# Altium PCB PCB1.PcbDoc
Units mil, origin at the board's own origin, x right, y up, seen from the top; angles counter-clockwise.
Board outline 3942.06 x 5904.05 mil, 2 copper layers (Top Layer, Bottom Layer); 24 components, 64 nets, 315 pads, 153 vias.
Unrouted connection lines stored in the file: 55.
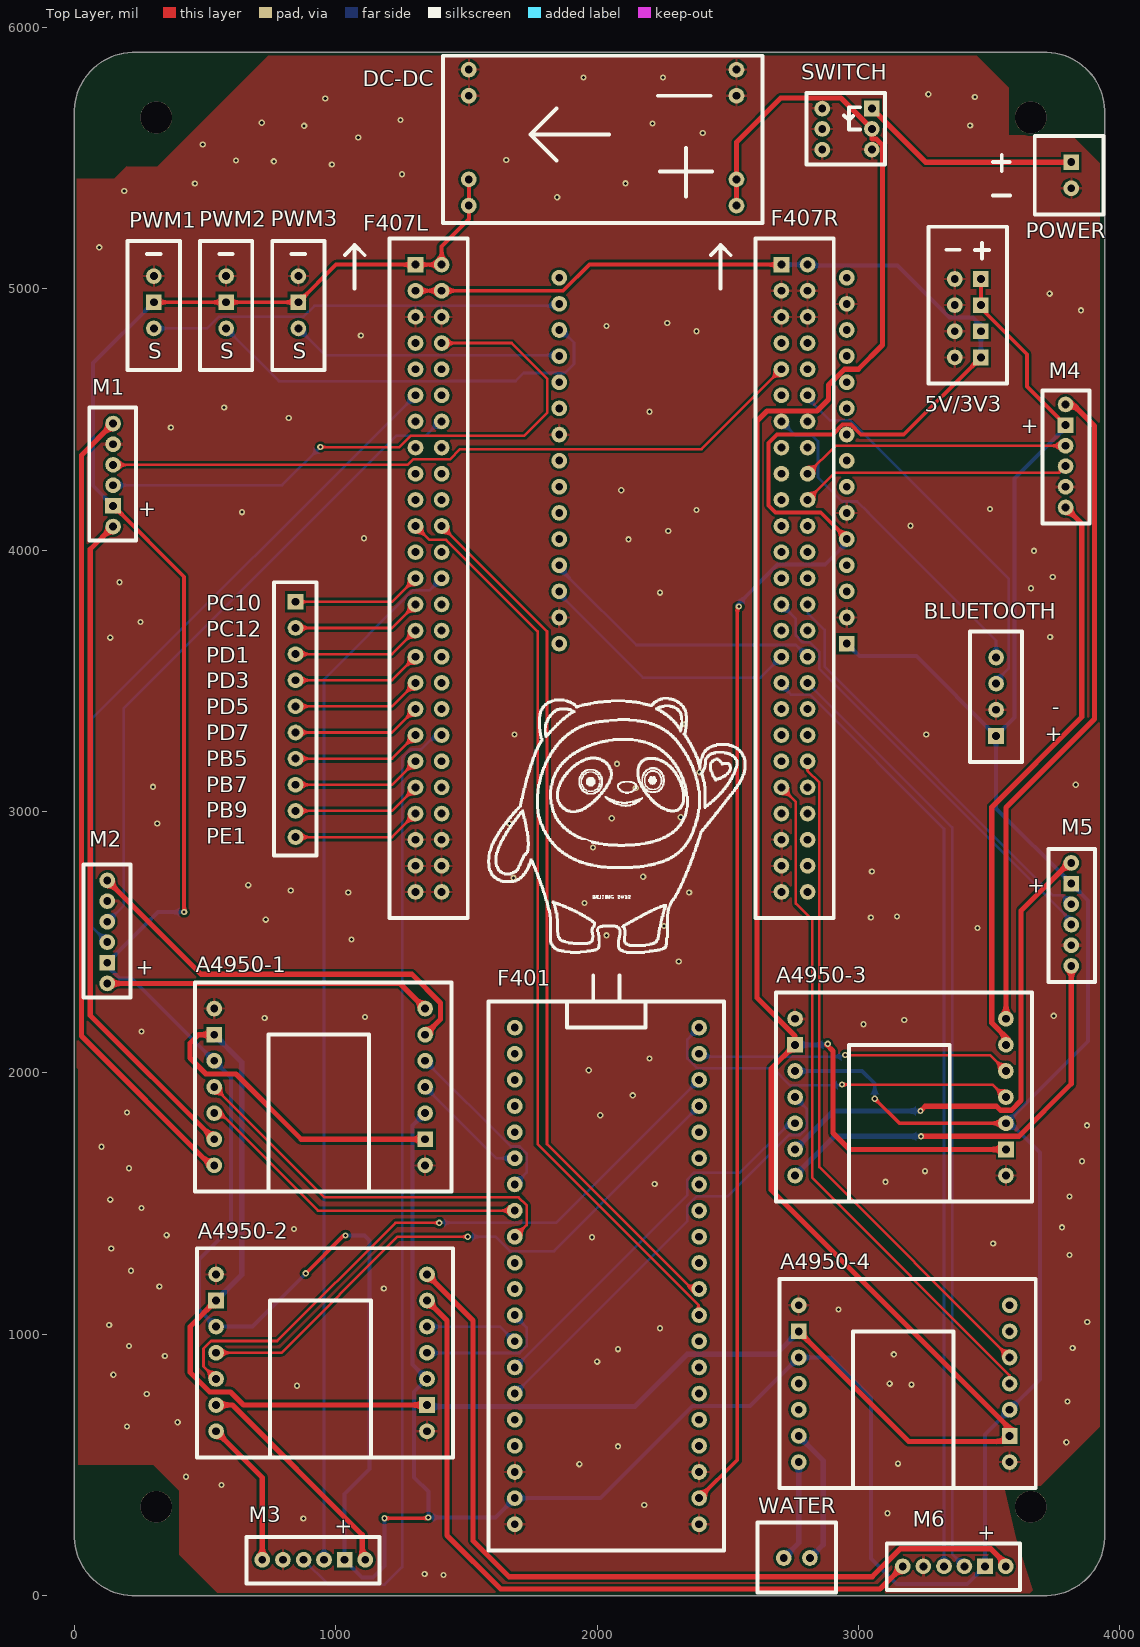
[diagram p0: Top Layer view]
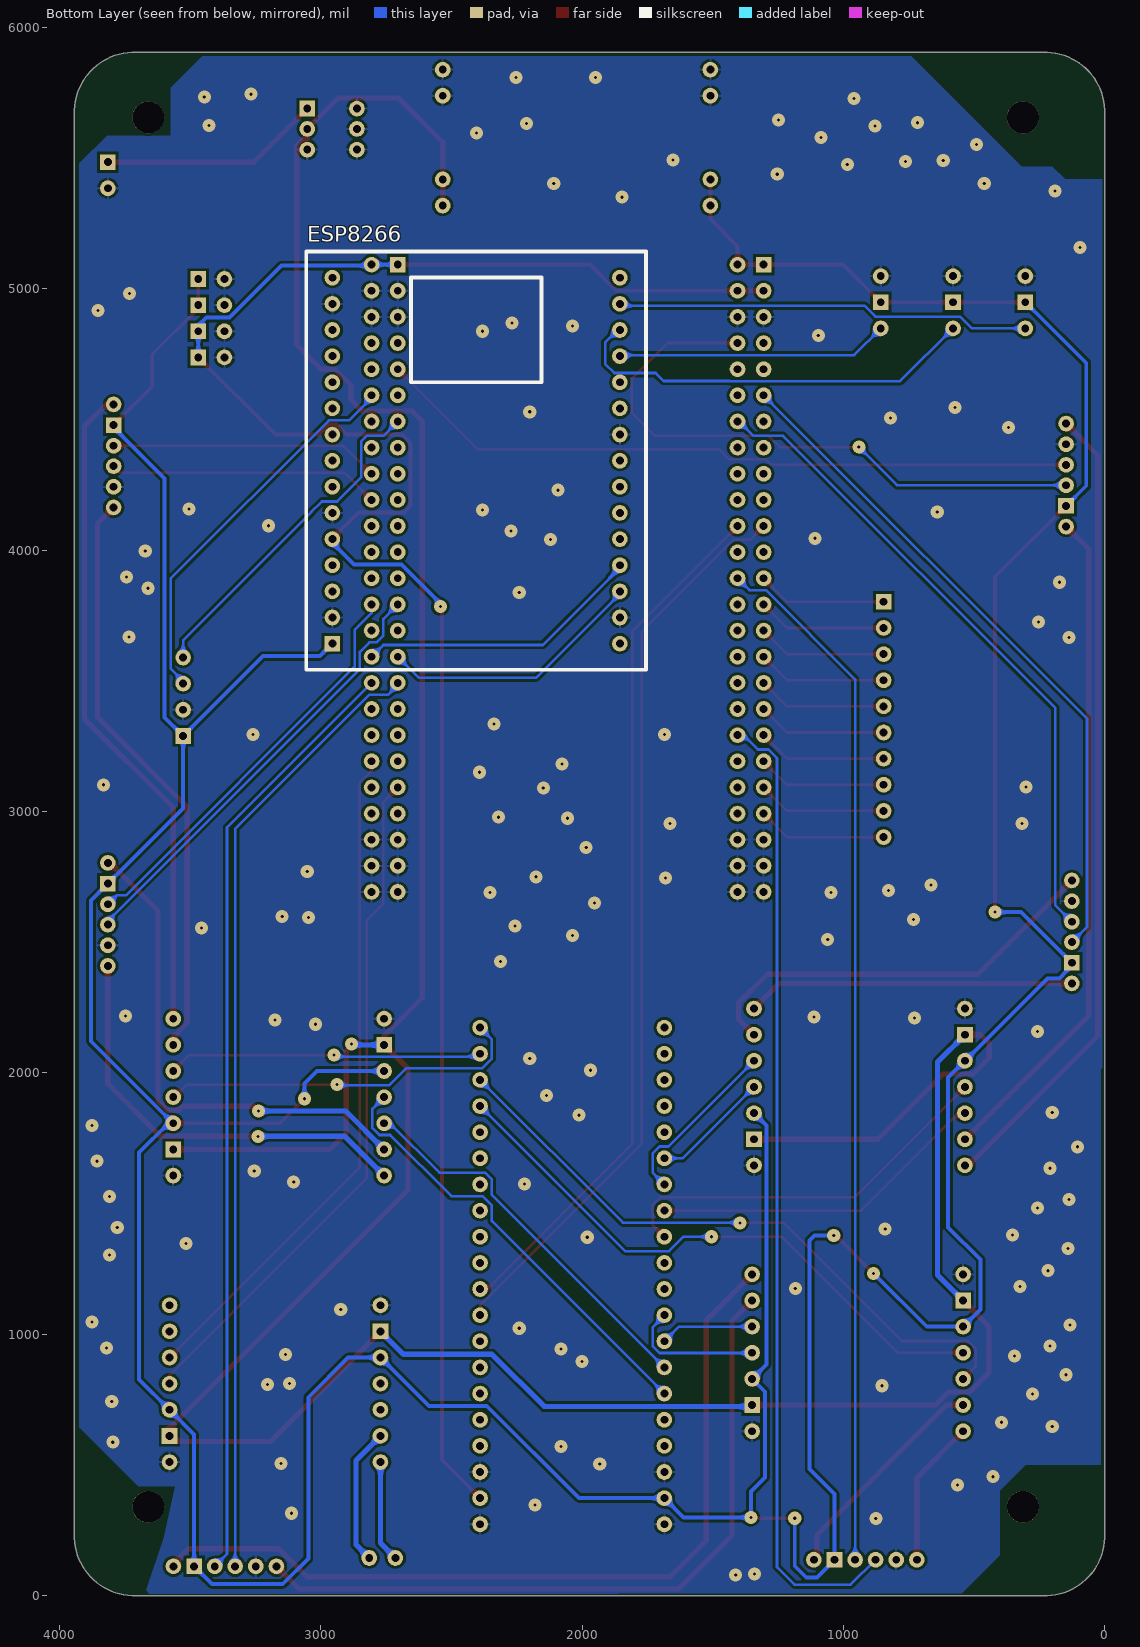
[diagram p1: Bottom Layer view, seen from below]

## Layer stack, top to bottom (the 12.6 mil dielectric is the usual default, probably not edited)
Top Solder: solder mask 0.4, Solder Resist, Dk 3.5
Top Layer: signal copper 1.4
Dielectric 1: dielectric 12.6, FR-4, Dk 4.8
Bottom Layer: signal copper 1.4
Bottom Solder: solder mask 0.4, Solder Resist, Dk 3.5

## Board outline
220,0 cw(c228.5,228.5) 0,237 0,236.11 0,5684 cw(c228.5,5675.5) 237,5904 3722.01,5904 cw(c3713.51,5675.5) 3942.01,5667 3942.01,5666 3942.01,219 3942,220 cw(c3713.5,228.5) 3705,0

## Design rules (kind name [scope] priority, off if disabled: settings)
Clearance [All] p1: gap=10 ignorepadtopadclearanceinfootprint=FALSE except(0.25: Arc-Arc Arc-Track Arc-SMDPad Arc-THPad Arc-Via Arc-Text Arc-Hole Track-Track Track-SMDPad Track-THPad Track-Via Track-Text Track-Hole SMDPad-SMDPad SMDPad-THPad SMDPad-Via SMDPad-Text SMDPad-Hole THPad-THPad THPad-Via THPad-Text THPad-Hole Via-Via Via-Text Via-Hole Text-Text Text-Hole)
HoleSize [All] p1: absolutevalues=TRUE maxlimit=130 minlimit=1 maxpercent=80.000 minpercent=20.000
PolygonConnect [All] p1: thpad.connectstyle=Relief thpad.reliefconductorwidth=10 thpad.reliefentries=4 thpad.polygonreliefangle="90 Angle" thpad.airgapwidth=10 smdpad.connectstyle=Relief smdpad.reliefconductorwidth=10 smdpad.reliefentries=4 smdpad.polygonreliefangle="90 Angle" smdpad.airgapwidth=10 via.connectstyle=Direct via.reliefconductorwidth=10 via.reliefentries=4 via.polygonreliefangle="90 Angle" via.airgapwidth=10
RoutingVias [All] p1: holewidth=28 width=50 viastyle="Through Hole" minholewidth=28 minwidth=50 maxholewidth=28 maxwidth=50
SilkToSolderMaskClearance [IsPad] p1: minsilkscreentomaskgap=7 clearancetoexposedcopper=TRUE
SolderMaskExpansion [All] p1: expansion=4
Width Width_4 [All] p1: maxlimit=20 minlimit=10 preferedwidth=10
Width Width_3 [InNet('3V3')] p2: maxlimit=15 minlimit=10 preferedwidth=15
Width Width_2 [InNet('5V')] p3: maxlimit=15 minlimit=15 preferedwidth=15
Width Width_1 [InNet('12V')] p4: maxlimit=20 minlimit=10 preferedwidth=20
Width [InNet('12V_IN')] p5: maxlimit=20 minlimit=10 preferedwidth=20
28 further rules are at their usual default settings.

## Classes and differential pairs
component class Sheet1: DC-DC POWER SWITCH

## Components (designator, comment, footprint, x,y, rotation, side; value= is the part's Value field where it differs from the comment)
*1 "PIN_HEADER" PIN_HEADER -9460,-15590 r0 top
*2 "POWER_HEADER" POWER_HEADER 3468,5137 r0 top
A4950-1 "A4950" A4950 962,2191 r180 top (schematic designator *5)
A4950-2 "A4950" A4950 969,1174 r180 top (schematic designator *6)
A4950-3 "A4950" A4950 3184,2152 r180 top (schematic designator *7)
A4950-4 "A4950" A4950 3198,1056 r180 top (schematic designator *8)
BLUETOOTH "HC-06" HC-06 3718,3582 r180 top (schematic designator *11)
DC-DC "DC-DC" DC-DC 1902,5412 r180 top (schematic designator *9)
ESP8266 "ESP8266" ESP 1894,3008 r180 bottom (schematic designator *22)
F401 "STM32F401" STM32F401CCU6 2290,273 r0 top (schematic designator *21)
F407L "STM32F407左" STM32F407左 1305,3992 r0 top (schematic designator *19)
F407R "STM32F407右" STM32F407左 2705,3992 r0 top locked (schematic designator *18)
M1 "ENCODER1" ENCODER1 148,4090 r0 top (schematic designator *15)
M2 "ENCODER2" ENCODER1 126,2342 r0 top (schematic designator *16)
M3 "ENCODER3" ENCODER1 1113,137 r90 top (schematic designator *17)
M4 "ENCODER4" ENCODER2 3813,4155 r0 top (schematic designator *12)
M5 "ENCODER5" ENCODER2 3835,2401 r0 top (schematic designator *13)
M6 "ENCODER6" ENCODER2 3161,91 r270 top (schematic designator *14)
POWER "POWER" POWER 3814,5384 r0 top (schematic designator *10)
PWM1 "PWM1" PWM 1004,3548 r0 top (schematic designator *20)
PWM2 "PWM2" PWM 1280.5,3548 r0 top (schematic designator *23)
PWM3 "PWM3" PWM 1557,3548 r0 top (schematic designator *24)
SWITCH "SWITCH" SIWITCH 2951,5689 r0 top (schematic designator *3)
WATER "WATER_MOTER" WATER_HEADER 2814,144 r90 top (schematic designator *4)

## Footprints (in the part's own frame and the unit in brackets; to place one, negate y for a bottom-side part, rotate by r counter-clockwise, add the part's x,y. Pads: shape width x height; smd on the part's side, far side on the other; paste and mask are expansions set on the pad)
A4950 [mil]
  round 60 hole 30: 1(-380,545) 3(-380,345) 4(-380,245) 5(-380,145) 6(-380,45) 7(-380,-55) 8(427,545) 9(427,445) 10(427,345) 11(427,245) 12(427,145) 14(427,-55)
  rect 60x60 hole 30: 2(-380,445) 13(427,45)
  silkscreen extent -480,-155 500,645
DC-DC [mil]
  round 60 hole 30: 1(-631,-426) 2(-631,-326) 3(-631,-6) 4(-631,94) 5(393,-426) 6(393,-326) 7(393,-6) 8(393,94)
  silkscreen extent -731,-479 492,160
ENCODER1 [mil]
  round 60 hole 30: 1(0,394) 2(0,315) 3(0,236) 4(0,158) 6(0,0)
  rect 60x60 hole 30: 5(0,79)
  silkscreen extent -91,-54 88,455
ENCODER2 [mil]
  round 60 hole 30: 1(-21,8) 2(-21,87) 3(-21,166) 4(-21,244) 6(-21,402)
  rect 60x60 hole 30: 5(-21,323)
  silkscreen extent -109,-53 70,456
ESP [mil]
  round 60 hole 30: 1(-1061,2034) 2(-1061,1934) 3(-1061,1834) 4(-1061,1734) 5(-1061,1634) 6(-1061,1534) 7(-1061,1434) 8(-1061,1334) 9(-1061,1234) 10(-1061,1134) 11(-1061,1034) 12(-1061,934) 13(-1061,834) 14(-1061,734) 16(39,2034) 17(39,1934) 18(39,1834) 19(39,1734) 20(39,1634) 21(39,1534) 22(39,1434) 23(39,1334) 24(39,1234) 25(39,1134) 26(39,1034) 27(39,934) 28(39,834) 29(39,734) 30(39,634)
  rect 60x60 hole 30: 15(-1061,634)
  silkscreen extent -1161,534 139,2134
HC-06 [mil]
  round 60 hole 30: 1(192,-7) 2(192,93) 3(192,193)
  rect 60x60 hole 30: 4(192,293)
  silkscreen extent 92,-107 292,393
PIN_HEADER [mil]
  rect 60x60 hole 30: 1(10306,19392)
  round 60 hole 30: 2(10306,19292) 3(10306,19192) 4(10306,19092) 5(10306,18992) 6(10306,18892) 7(10306,18792) 8(10306,18692) 9(10306,18592) 10(10306,18492)
  silkscreen extent 10224,18422 10386,19467
POWER [mil]
  rect 60x60 hole 30: 1(0,100)
  round 60 hole 30: 2(0,0)
  silkscreen extent -300,-100 123,200
POWER_HEADER [mil]
  rect 60x60 hole 30: 1(0,-100) 2(0,-200) 3(0,-300) 4(0,-400)
  round 60 hole 30: 5(-100,-100) 6(-100,-200) 7(-100,-300) 8(-100,-400)
  silkscreen extent -200,-500 100,100
PWM [mil]
  round 60 hole 30: 1(-700,1500) 3(-700,1300)
  rect 60x60 hole 30: 2(-700,1400)
  silkscreen extent -800,1141 -600,1634
SIWITCH [mil]
  rect 60x60 hole 30: 1(100,0)
  round 60 hole 30: 2(100,-78) 3(100,-157) 4(-90,0) 5(-90,-78) 6(-90,-157)
  silkscreen extent -150,-214 150,60
STM32F401CCU6 [mil]
  round 60 hole 30: 1(-605,1900) 2(-605,1800) 3(-605,1700) 4(-605,1600) 5(-605,1500) 6(-605,1400) 7(-605,1300) 8(-605,1200) 9(-605,1100) 10(-605,1000) 11(-605,900) 12(-605,800) 13(-605,700) 14(-605,600) 15(-605,500) 16(-605,400) 17(-605,300) 18(-605,200) 19(-605,100) 20(-605,0) 21(100,1900) 22(100,1800) 23(100,1700) 24(100,1600) 25(100,1500) 26(100,1400) 27(100,1300) 28(100,1200) 29(100,1100) 30(100,1000) 31(100,900) 32(100,800) 33(100,700) 34(100,600) 35(100,500) 36(100,400) 37(100,300) 38(100,200) 39(100,100) 40(100,0)
  silkscreen extent -705,-100 195,2100
STM32F407左 [mil]
  rect 60x60 hole 30: 1(0,1100)
  round 60 hole 30: 2(0,1000) 3(0,900) 4(0,800) 5(0,700) 6(0,600) 7(0,500) 8(0,400) 9(0,300) 10(0,200) 11(0,100) 12(0,0) 13(0,-100) 14(0,-200) 15(0,-300) 16(0,-400) 17(0,-500) 18(0,-600) 19(0,-700) 20(0,-800) 21(0,-900) 22(0,-1000) 23(100,1100) 24(100,1000) 25(100,900) 26(100,800) 27(100,700) 28(100,600) 29(100,500) 30(100,400) 31(100,300) 32(100,200) 33(100,100) 34(100,0) 35(100,-100) 36(100,-200) 37(100,-300) 38(100,-400) 39(100,-500) 40(100,-600) 41(100,-700) 42(100,-800) 43(100,-900) 44(100,-1000) 45(0,-1100) 46(0,-1200) 47(0,-1300) 48(100,-1100) 49(100,-1200) 50(100,-1300)
  silkscreen extent -270,-1400 200,1200
WATER_HEADER [mil]
  round 60 hole 30: 1(0,100) 2(0,0)
  silkscreen extent -132,-100 135,200

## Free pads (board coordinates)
  round 122 hole 122: 75(313,340) 75(313,5655) 75(3659,340) 75(3659,5655)

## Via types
v1: diameter 24/50 (per signal layer), hole 12, Top Layer to Bottom Layer, 153 vias

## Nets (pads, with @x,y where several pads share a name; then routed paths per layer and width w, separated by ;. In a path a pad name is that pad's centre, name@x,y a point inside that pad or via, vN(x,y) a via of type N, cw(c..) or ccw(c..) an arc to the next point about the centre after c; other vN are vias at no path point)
3V3: *2.3 *2.4 ESP8266.11 F401.39 F407L.2 F407L.24 F407R.1 F407R.23 | length 7991
  Top Layer w15: F407L.2 F407L.24 1870,4992 1970,5092 F407R.1 ; F401.39 2536,519 v1@2536,3784 ; ESP8266.11@2964,4036 2855.5,4144.5 2681.5,4144.5 2656,4170 2656,4410.18 2687.82,4442 2901.61,4442 2939.36,4479.75 2970.64,4479.75 3008.39,4442 3173,4442 *2.4
  Bottom Layer w15: v1@2534,3788.18 2690.32,3944.5 2872.5,3944.5 ESP8266.11@2951,4023 ; F407R.1 F407R.23 2809,5088 3149.82,5088 3348.32,4889.5 3437.5,4889.5 3468,4859 *2.3 *2.4
  other v1: 2542,3784
5V: *2.1 *2.2 A4950-1.3 A4950-1.12 A4950-2.3 A4950-2.12 A4950-3.3 A4950-3.12 A4950-4.3 A4950-4.12 BLUETOOTH.4 DC-DC.7 DC-DC.8 ESP8266.15 F401.19 F407L.1 F407L.23 M1.5 M2.5 M3.5 M4.5 M5.5 M6.5 PWM1.2 PWM2.2 PWM3.2 | length 20760.1
  Top Layer w15: M1.5 149,4169 420,3898 v1(420,2615) ; PWM1.2 PWM2.2 PWM3.2 1001,5092 F407L.1 F407L.23 1405,5162 1509,5266 DC-DC.8 DC-DC.7 ; v1(885,1233) v1@1027,1375 ; v1(1186,296) 1351,296 v1(1354,299) ; A4950-1.3 A4950-1.3@1345.5,1842.5 ; v1(3062,1901) 3156,1807 A4950-3.3 ; *2.1 *2.2 3462,4931 3644,4749 3644,4626 M4.5
  Bottom Layer w15: M2.5 126,2408 144.5,2389.5 145.68,2389.5 173.5,2361.68 219.32,2361.68 A4950-1.12 599,1982 599,1409 476,1286 476,1095 A4950-2.12 681,1029 v1(885,1233) ; M2.5@127,2422 320,2615 v1(420,2615) ; M1.5 71,4246 71,4715 PWM1.2 ; v1(1037,1378) 1110,1378 1129,1359 1129,484 1034,389 M3.5 1101,70 1142,70 1186,114 v1(1186,296) v1@1182,296 ; A4950-1.3 1294,1798 1294,884 A4950-2.3 1300,780 1300,452 1354,398 v1(1354,299) 1611,299 F401.19 ; F401.19@1675,383 F401.19 ; A4950-3.12 3014,2007 3062,1959 v1(3062,1901) ; ESP8266.15 3003,3594 3221,3594 BLUETOOTH.4 ; M4.5@3792,4498 M4.5 3792,4469 3596.5,4273.5 3596.5,3359.5 BLUETOOTH.4 ; F401.19 2012,373 2364.5,725.5 2585.5,725.5 A4950-4.12 2895,911 3047,759 3047,142 3145,44 3416,44 M6.5 3484,617 A4950-4.3 3694,827 3694,1695 3582,1807 A4950-3.3 3878,2121 3878,2660 M5.5 3526,3012 BLUETOOTH.4
12V: A4950-1.2 A4950-1.13 A4950-2.2 A4950-2.13 A4950-3.2 A4950-3.13 A4950-4.2 A4950-4.13 DC-DC.3 DC-DC.4 SWITCH.2 | length 13965.3
  Top Layer w20: A4950-1.13 475,2146 442,2113 442,2057 503,1996 618,1996 868,1746 A4950-1.2 ; A4950-2.13 443,1030 443,854 518,779 597.43,779 647.43,729 A4950-2.2 ; DC-DC.4 DC-DC.3 2533,5560 2702.25,5729.25 2932.75,5729.25 SWITCH.2 3051,5572.25 3067.67,5572.25 3091.25,5548.67 3091.25,4784.25 2999,4692 2946,4692 2885,4631 2885,4576 2841.25,4532.25 2650,4532.25 2611,4493.25 2611,2287 2757,2141 A4950-3.13 2666,2016 2666,1552.29 3578,640.29 A4950-4.2 3550,590 3192,590 A4950-4.13 ; v1@2878.5,2107.5 2902,2084 2902,1770 2965,1707 A4950-3.2
  Bottom Layer w20: A4950-1.13 640,2041 640,1227 A4950-2.13 ; A4950-2.2 1355,723 2144,723 2344,923 2683,923 A4950-4.13 ; A4950-3.13 v1@2865,2107
  other v1: 2882,2111
12V_IN: POWER.1 SWITCH.1 | length 847.9
  Top Layer w20: SWITCH.1 3256,5484 POWER.1
401R: F401.31 F407L.33 | length 3343.4
  Top Layer w10: F407L.33 1808,3689 1808,1727 2362,1173 F401.31
401T: F401.32 F407L.11 | length 3515.1
  Top Layer w10: F407L.11 1358,4039 1422,4039 1772,3689 1772,1727.36 2388,1111.36 F401.32@2388,1063
EN1A: F407L.26 M1.4 | length 2366.9
  Top Layer w10: v1(941,4394) 1243.36,4394 1286.36,4437 1721,4437 1809,4525 1809,4655.62 1672.62,4792 F407L.26
  Bottom Layer w10: M1.4 795,4248 v1(941,4394)
EN1B: F407R.5 M1.3 | length 2708.6
  Top Layer w10: M1.3 1275.36,4326 1296.36,4347 1437,4347 1476,4386 2399,4386 F407R.5
EN2A: F407L.6 M2.4 | length 2628.4
  Bottom Layer w10: M2.4 68,2558 68,3355 F407L.6
EN2B: F407L.29 M2.3 | length 2495.2
  Bottom Layer w10: M2.3 189,2641 189,3395 1231,4437 1343,4437 F407L.29@1390,4484
EN3A: F407L.35 M3.4 | length 3978.7
  Bottom Layer w10: M3.4 955,3505.64 1296.36,3847 1360,3847 F407L.35
EN3B: F407L.41 M3.3 | length 3735.2
  Bottom Layer w10: M3.3 972,42 1187,42 1254,109 1254,2667.36 1254,3204.64 1286.36,3237 1327,3237 1392,3302 1395,3302 F407L.41
EN4A: F407R.31 M4.4 | length 1031.3
  Top Layer w10: F407R.31 2912,4399 M4.4
EN4B: F407R.32 M4.3 | length 1040.4
  Top Layer w10: F407R.32 2909,4296 3767,4296 M4.3
EN5A: F407R.36 M5.4 | length 1585.7
  Bottom Layer w10: F407R.36 2805,3759 2870,3694 2870,3553.64 3744.64,2679 3780,2679 M5.4
EN5B: F407R.14 M5.3 | length 1700.3
  Bottom Layer w10: F407R.14 2760,3737 2760,3673.36 2786.36,3647 2813.64,3647 2850,3610.64 2850,3545.36 3814,2581.36 M5.3
EN6A: F407R.39 M6.4 | length 3628.5
  Bottom Layer w10: F407R.39 3358,2939 3358,159 M6.4
EN6B: F407R.17 M6.3 | length 3680.2
  Bottom Layer w10: F407R.17 2705,3483 2741,3447 2813.64,3447 3327,2933.64 M6.3
ESPR: ESP8266.27 F407R.38 | length 1100.8
  Bottom Layer w10: 1893,3894 2150,3637 2760,3637 F407R.38
  Bottom Layer w15: ESP8266.27 1855,3932 1893,3894
ESPT: ESP8266.28 F407R.16 | length 1025.7
  Bottom Layer w10: ESP8266.28 1855,3832 2175,3512 2625,3512 F407R.16
GND: *2.5 *2.6 *2.7 *2.8 A4950-1.1 A4950-1.14 A4950-2.1 A4950-2.14 A4950-3.1 A4950-3.14 A4950-4.1 A4950-4.14 BLUETOOTH.3 DC-DC.1 DC-DC.2 DC-DC.5 DC-DC.6 ESP8266.2 ESP8266.10 ESP8266.14 ESP8266.22 ESP8266.29 F401.18 F401.20 F401.38 F401.40 F407L.3 F407L.25 F407L.45 F407L.46 F407L.47 F407L.48 F407L.49 F407L.50 F407R.2 F407R.3 F407R.24 F407R.25 F407R.45 F407R.46 F407R.47 F407R.48 F407R.49 F407R.50 M1.2 M2.2 M3.2 M4.2 M5.2 M6.2 POWER.2 PWM1.1 PWM2.1 PWM3.1 SWITCH.3 SWITCH.4 SWITCH.5 SWITCH.6
  other v1: 1412,79 1340,83 876,295 3111,315 2180,347 563,423 427,455 1932,503 3151,505 2080,571 3795,587 201,647 395,663 3799,743 277,771 852,803 3203,807 3119,811 149,845 2000,895 346,917 3135,923 2080,943 3819,947 209,955 2240,1023 133,1035 3875,1047 2923,1095 1184,1175 325,1183 217,1243 3807,1303 141,1328 3515,1347 1980,1371 353,1379 840,1403 3778,1409 257,1483 137,1515 3807,1527 2220,1575 3103,1583 3254,1624 209,1635 3855,1662 104,1717 3874,1799 2012,1838 201,1848 2136,1914 1968,2010 2200,2055 257,2158 3019,2186 3175,2202 728,2210 1112,2214 3747,2218 2312,2426 1060,2510 2036,2526 3455,2554 2256,2562 732,2586 3047,2594 3147,2598 1952,2650 1048,2690 2352,2690 828,2698 665,2718 1680,2746 2176,2750 3051,2770 1984,2862 317,2954 1664,2954 2056,2974 2320,2978 2148,3090 301,3094 3831,3102 2392,3150 2076,3182 1684,3294 3259,3294 2336,3334 137,3665 3733,3667 253,3725 2240,3837 3660,3854 173,3877 3743,3897 3671,3997 2120,4041 1108,4045 2272,4073 3199,4093 641,4145 2380,4153 3503,4157 2092,4229 369,4469 820,4505 2200,4529 573,4545 1096,4821 2380,4837 2036,4857 2268,4869 3851,4917 3731,4981 95,5158 1847,5350 191,5374 461,5402 2108,5403 1253,5438 985,5475 763,5487 618,5490 1652,5492 491,5552 1086,5578 2404,5596 879,5623 3427,5624 2212,5632 717,5635 1248,5645 960,5728 3445,5733 3267,5744 1948,5808 2252,5808
H1: *1.1 F407L.13 | length 496.3
  Top Layer w10: *1.1 1215,3802 F407L.13
H2: *1.2 F407L.14 | length 496.3
  Top Layer w10: *1.2 1215,3702 F407L.14
H3: *1.3 F407L.15 | length 496.3
  Top Layer w10: *1.3 1215,3602 F407L.15
H4: *1.4 F407L.16 | length 496.3
  Top Layer w10: *1.4 1215,3502 F407L.16
H5: *1.5 F407L.17 | length 496.3
  Top Layer w10: *1.5 1215,3402 F407L.17
H6: *1.6 F407L.18 | length 496.3
  Top Layer w10: *1.6 1215,3302 F407L.18
H7: *1.7 F407L.19 | length 496.3
  Top Layer w10: *1.7 1215,3202 F407L.19
H8: *1.8 F407L.20 | length 496.3
  Top Layer w10: *1.8 1215,3102 F407L.20
H9: *1.9 F407L.21 | length 496.3
  Top Layer w10: *1.9 1215,3002 F407L.21
H10: *1.10 F407L.22 | length 496.3
  Top Layer w10: *1.10 1215,2902 F407L.22
HR: BLUETOOTH.1 F407R.7 | length 1319
  Bottom Layer w10: F407R.7 2760,4437 2823.64,4437 2845,4415.64 2845,4278 2937,4186 2995,4186 3038,4143 ; 3034,4146 3526,3654 BLUETOOTH.1
HT: BLUETOOTH.2 F407R.28 | length 1500.9
  Bottom Layer w10: F407R.28 2805,4582 2891,4496 2968.64,4496 3574,3890.64 3574,3547 BLUETOOTH.2@3521,3494 ; BLUETOOTH.2@3514,3487 BLUETOOTH.2@3521,3494 ; BLUETOOTH.2 BLUETOOTH.2@3521,3494
M11: A4950-1.4 F401.6 | length 456.1
  Bottom Layer w10: A4950-1.4 1615,1673 F401.6
M12: A4950-1.5 F401.7 | length 672.1
  Bottom Layer w10: A4950-1.5 1670,1718 1703.64,1718 1730,1691.64 1730,1618 F401.7
M21: A4950-1.10 F401.8 | length 1304.5
  Top Layer w10: A4950-1.10 559,1846 932,1473 F401.8
M22: A4950-1.11 F401.9 | length 1521.9
  Top Layer w10: A4950-1.11 957,1524 1700,1524 1730,1494 1730,1418 F401.9
M31: A4950-2.4 F401.12 | length 530.2
  Bottom Layer w10: A4950-2.4 1349,928 1703.64,928 1730,954.36 1730,1026 1685,1071 F401.12
M32: A4950-2.5 F401.13 | length 359.2
  Bottom Layer w10: A4950-2.5 1629,1029 F401.13
M41: A4950-3.10 F401.14 | length 1493.2
  Bottom Layer w10: F401.14 2345,1533 2345,1591.64 2371.36,1618 2546,1618 2735,1807 A4950-3.10
M42: A4950-3.11 F401.15 | length 1709.2
  Bottom Layer w10: F401.15 2345,1433 2345,1491.64 2381.36,1528 2500,1528 2734,1762 2775.64,1762 2802,1788.36 2802,1862 A4950-3.11
M51: A4950-3.4 F401.21 | length 1410.2
  Top Layer w10: v1(2937,1955) 3512,1955 A4950-3.4@3554,1913
  Bottom Layer w10: F401.21 2345,2128 2345,2054.36 2381.36,2018 2672.36,2018 2738.36,1952 2938,1952 v1(2937,1955)
M52: A4950-3.5 F401.22 | length 1204.7
  Top Layer w10: v1(2949,2068) 3503,2068 A4950-3.5
  Bottom Layer w10: F401.22 2401,2062 2929,2062 v1(2949,2068)
M61: A4950-2.10 F401.23 | length 2451.1
  Top Layer w10: A4950-2.10 494,877 494,944.64 523.36,974 776,974 1228,1426 v1(1396,1426)
  Bottom Layer w10: v1@1402,1427 1844,1427 F401.23
M62: A4950-2.11 F401.24 | length 2284.6
  Top Layer w10: A4950-2.11 792,929 1236,1373 v1(1505,1373)
  Bottom Layer w10: v1(1505,1373) 1611.36,1373 1666.36,1318 1835,1318 F401.24
MO11: A4950-1.8 M1.1 | length 3106.2
  Top Layer w20: M1.1 27,4363 27,2141 522,1646 A4950-1.8
MO12: A4950-1.9 M1.6 | length 2576.4
  Top Layer w20: M1.6 61,4003 61,2220 A4950-1.9
MO21: A4950-1.6 M2.1 | length 1614.7
  Top Layer w20: M2.1 485,2377 1291,2377 1401,2267 1401,2205 A4950-1.6
MO22: A4950-1.7 M2.6 | length 1255.8
  Top Layer w20: M2.6 1246,2342 A4950-1.7
MO31: A4950-2.8 M3.1 | length 565.3
  Top Layer w20: A4950-2.8 719,452 M3.1
MO32: A4950-2.9 M3.6 | length 886.4
  Top Layer w10: M3.6@1101,149 M3.6
  Top Layer w20: A4950-2.9 605,729 1101,233 M3.6@1101,149 ; M3.6 M3.6@1113,158
MO41: A4950-3.6 M4.1 | length 2246.5
  Top Layer w20: A4950-3.6 3564,2136.29 3510,2190.29 3510,3017 3854,3361 3854,4101 M4.1
MO42: A4950-3.7 M4.6 | length 2552.8
  Top Layer w20: A4950-3.7 3564,3015 3903,3354 3903,4474 3820,4557 M4.6
MO51: A4950-3.8 M5.1 | length 1653.4
  Top Layer w20: v1(3239,1757) 3613,1757 3814,1958 M5.1
  Bottom Layer w20: A4950-3.8 2907,1757 v1(3239,1757)
MO52: A4950-3.9 M5.6 | length 1948.7
  Top Layer w20: v1(3237,1854) 3255,1872 3528.29,1872 3543.29,1857 3584.71,1857 3622,1894.29 3622,2620.28 3804.72,2803 M5.6
  Bottom Layer w20: A4950-3.9 2904,1854 v1(3237,1854)
MO61: A4950-2.6 M6.1 | length 2794.8
  Top Layer w20: A4950-2.6 1426,1052 1426,230 1631,25 3082,25 M6.1
MO62: A4950-2.7 M6.6 | length 3269.9
  Top Layer w20: A4950-2.7 1525,1053 1525,210 1663,72 3052,72 3159,179 3507,179 3567.61,118.39 M6.6@3567.61,109.61
PWM1: ESP8266.17 PWM1.3 | length 1589.9
  Bottom Layer w10: PWM1.3 508,4848 553,4893 877,4893 918,4934 1847,4934 ESP8266.17
PWM2: ESP8266.18 PWM2.3 | length 1593.8
  Bottom Layer w10: PWM2.3 782.5,4646 1438,4646 1437,4647 1688,4647 1718.25,4677.25 1876.25,4677.25 1911.5,4712.5 1911.5,4793.5 ESP8266.18@1863,4842
PWM3: ESP8266.19 PWM3.3 | length 1039
  Bottom Layer w10: PWM3.3 959,4746 1841,4746 ESP8266.19@1850,4737
WATER1: A4950-4.4 F407R.21 | length 2642.6
  Top Layer w10: F407R.21 2760,3037 2760,2647 2823,2584 2823,1598 3578,843 A4950-4.4
WATER2: A4950-4.5 F407R.42 | length 2601.2
  Top Layer w10: F407R.42 2805,3155.64 2850,3110.64 2850,1639 A4950-4.5
WATERO1: A4950-4.8 WATER.1 | length 390.6
  Bottom Layer w20: WATER.1 2771,201 A4950-4.8
WATERO2: A4950-4.9 WATER.2 | length 527.1
  Bottom Layer w20: A4950-4.9 2865,517 2865,195 WATER.2
pads on no net: A4950-4.6 A4950-4.7 A4950-4.10 A4950-4.11 ESP8266.1 ESP8266.3 ESP8266.4 ESP8266.5 ESP8266.6 ESP8266.7 ESP8266.8 ESP8266.9 ESP8266.12 ESP8266.13 ESP8266.16 ESP8266.20 ESP8266.21 ESP8266.23 ESP8266.24 ESP8266.25 ESP8266.26 ESP8266.30 F401.1 F401.2 F401.3 F401.4 F401.5 F401.10 F401.11 F401.16 F401.17 F401.25 F401.26 F401.27 F401.28 F401.29 F401.30 F401.33 F401.34 F401.35 F401.36 F401.37 F407L.4 F407L.5 F407L.7 F407L.8 F407L.9 F407L.10 F407L.12 F407L.27 F407L.28 F407L.30 F407L.31 F407L.32 F407L.34 F407L.36 F407L.37 F407L.38 F407L.39 F407L.40 F407L.42 F407L.43 F407L.44 F407R.4 F407R.6 F407R.8 F407R.9 F407R.10 F407R.11 F407R.12 F407R.13 F407R.15 F407R.18 F407R.19 F407R.20 F407R.22 F407R.26 F407R.27 F407R.29 F407R.30 F407R.33 F407R.34 F407R.35 F407R.37 F407R.40 F407R.41 F407R.43 F407R.44

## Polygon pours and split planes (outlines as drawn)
GND on Top Layer "Top Layer-GND" (solid, remove dead copper, pour order 36): 201,5467 317,5467 741,5891 3452,5891 3574,5769 3574,5587 3816,5587 3923,5480 3923,646 3697,420 3556,420 3601,221 3667,21 3655,9 1864,9 1862,11 547,11 402,156 402,401 302,501 15,501 15,2014 9,2020 9,2057 10,2058 10,5420 152,5420 200,5468
no net on Top Layer "Top Layer-No Net 1" (solid, pour order 32): 115,5481
no net on Top Layer "Top Layer-No Net 2" (solid, pour order 30): 126,5485
no net on Top Layer "Top Layer-No Net" (solid, pour order 4): -12,28
GND on Bottom Layer "Bottom Layer-GND" (solid, remove dead copper, pour order 34): 201,5466 317,5466 741,5890 3452,5890 3574,5768 3574,5586 3816,5586 3923,5479 3923,645 3697,419 3556,419 3601,220 3667,20 3655,8 1864,8 1862,10 547,10 402,155 402,401 303,500 15,500 15,2013 9,2019 9,2056 10,2057 10,5419 152,5419 200,5467
no net on Bottom Layer "Bottom Layer-No Net 1" (solid, pour order 26): 495,5890
no net on Bottom Layer "Bottom Layer-No Net" (solid, pour order 16): -21,5898

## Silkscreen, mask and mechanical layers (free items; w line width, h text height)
Top Overlay:
  drawing of 3503 lines, arcs and shapes, not listed
  text "5V/3V3" at 3254,4529 h60
Mechanical 1:
  lines w10: 0,236.11 0,5684 cw(c228.5,5675.5) 237,5904 3722.01,5904 cw(c3713.51,5675.5) 3942.01,5667 ; 0,237 ccw(c228.5,228.5) 220,0 3705,0 ccw(c3713.5,228.5) 3942,220 ; 3942.01,219 3942.01,5666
